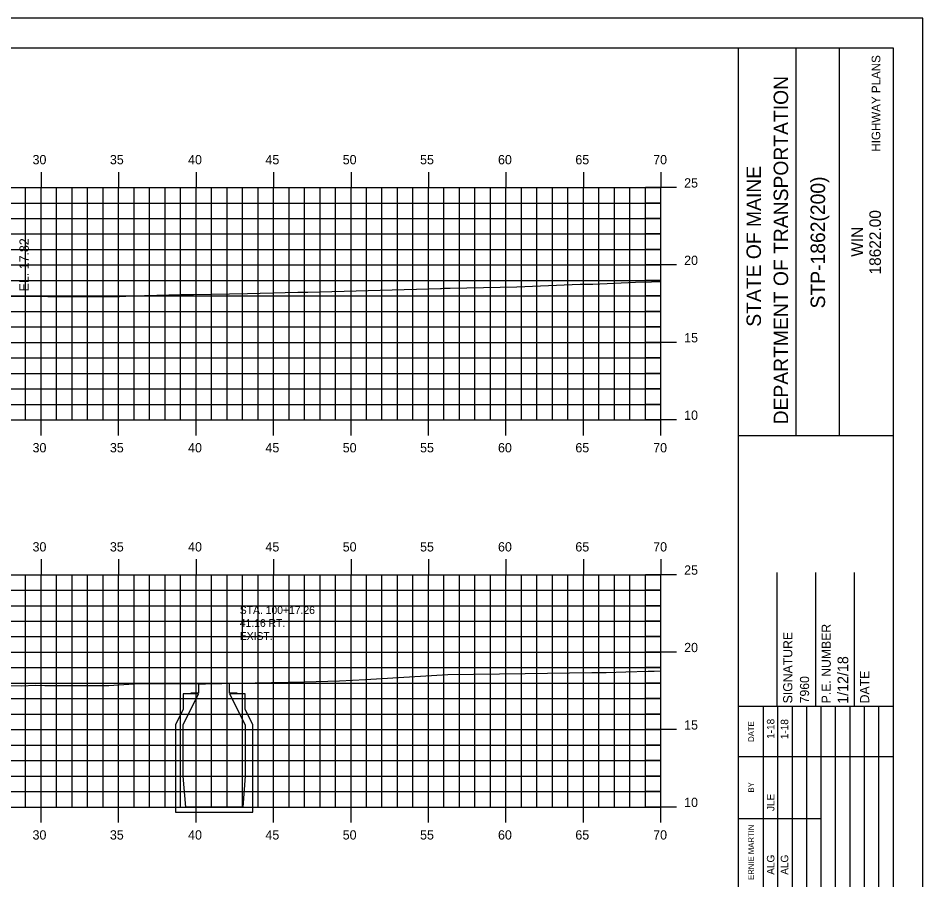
# Model space of a CAD drawing. Extents: x 1023237 to 1023407, y 394697 to 394807.
# Drawn here: x 1023348.2 to 1023406.6, y 394750.9 to 394806.5 of the extents above; entities that cross this region are included whole.
import ezdxf

# ---------------------------------------------------------------- set-up
doc = ezdxf.new("R2010")
doc.units = 0
for name, color, linetype in [('ANNOTATION', 7, 'Continuous'), ('BORDER', 7, 'Continuous'), ('D_Text_Monospaced', 7, 'Continuous'), ('H_V ANNOTATION', 7, 'Continuous'), ('HIGHWAY_TITLE', 7, 'Continuous'), ('MAJOR', 7, 'Continuous'), ('MINOR', 7, 'Continuous'), ('PLOT BOUNDARY', 7, 'Continuous'), ('S_Drainage_CB', 7, 'Continuous'), ('S_Roadway_Centerline', 7, 'Continuous')]:
    doc.layers.add(name, color=color, linetype=linetype)

msp = doc.modelspace()

# ---------------------------------------------------------------- linework, layer by layer
at = {"layer": 'BORDER'}
for p, q in [((1023404.664, 394804.607), (1023244.664, 394804.607)), ((1023394.664, 394699.607), (1023394.664, 394804.61)), ((1023398.392, 394779.604), (1023398.392, 394804.604)), ((1023401.187, 394779.604), (1023401.187, 394804.604)), ((1023404.664, 394699.607), (1023404.664, 394804.607)), ((1023394.664, 394779.601), (1023404.664, 394779.601)), ((1023397.164, 394762.11), (1023397.164, 394770.757)), ((1023399.664, 394762.11), (1023399.664, 394770.757)), ((1023402.164, 394762.11), (1023402.164, 394770.757)), ((1023394.664, 394762.11), (1023404.664, 394762.11))]:
    msp.add_line(p, q, dxfattribs=at)
for points in [[(1023396.278, 394758.86), (1023396.278, 394762.11)], [(1023397.211, 394744.613), (1023397.211, 394762.11)], [(1023398.143, 394762.11), (1023398.143, 394744.613)], [(1023399.074, 394744.613), (1023399.074, 394762.11)], [(1023400.006, 394744.613), (1023400.006, 394762.11)], [(1023400.938, 394744.613), (1023400.938, 394762.11)], [(1023401.869, 394744.613), (1023401.869, 394762.11)], [(1023402.801, 394744.613), (1023402.801, 394762.11)], [(1023403.733, 394744.613), (1023403.733, 394762.11)], [(1023396.279, 394744.613), (1023396.279, 394761.404)], [(1023394.664, 394758.86), (1023404.664, 394758.86)], [(1023394.664, 394754.86), (1023396.279, 394754.86)], [(1023396.278, 394754.86), (1023400.005, 394754.86)]]:
    msp.add_lwpolyline(points, dxfattribs=at)
at = {"layer": 'MAJOR'}
for p, q in [((1023349.663, 394796.609), (1023349.663, 394795.607)), ((1023354.663, 394796.609), (1023354.663, 394795.607)), ((1023359.663, 394796.609), (1023359.663, 394795.607)), ((1023364.663, 394796.609), (1023364.663, 394795.607)), ((1023369.663, 394796.609), (1023369.663, 394795.607)), ((1023374.663, 394796.609), (1023374.663, 394795.607)), ((1023379.663, 394796.609), (1023379.663, 394795.607)), ((1023384.663, 394796.609), (1023384.663, 394795.607)), ((1023389.663, 394796.609), (1023389.663, 394795.607)), ((1023249.663, 394795.607), (1023389.663, 394795.607)), ((1023349.663, 394780.607), (1023349.663, 394795.607)), ((1023354.663, 394780.607), (1023354.663, 394795.607)), ((1023359.663, 394780.607), (1023359.663, 394795.607)), ((1023364.663, 394780.607), (1023364.663, 394795.607)), ((1023369.663, 394780.607), (1023369.663, 394795.607)), ((1023374.663, 394780.607), (1023374.663, 394795.607)), ((1023379.663, 394780.607), (1023379.663, 394795.607)), ((1023384.663, 394780.607), (1023384.663, 394795.607)), ((1023390.665, 394795.607), (1023388.661, 394795.607)), ((1023389.663, 394780.607), (1023389.663, 394795.607)), ((1023249.663, 394790.607), (1023389.663, 394790.607)), ((1023390.665, 394790.607), (1023388.661, 394790.607)), ((1023249.663, 394785.607), (1023389.663, 394785.607)), ((1023390.665, 394785.607), (1023388.661, 394785.607)), ((1023249.663, 394780.607), (1023389.663, 394780.607)), ((1023349.663, 394779.605), (1023349.663, 394780.607)), ((1023354.663, 394779.605), (1023354.663, 394780.607)), ((1023359.663, 394779.605), (1023359.663, 394780.607)), ((1023364.663, 394779.605), (1023364.663, 394780.607)), ((1023369.663, 394779.605), (1023369.663, 394780.607)), ((1023374.663, 394779.605), (1023374.663, 394780.607)), ((1023379.663, 394779.605), (1023379.663, 394780.607)), ((1023384.663, 394779.605), (1023384.663, 394780.607)), ((1023390.665, 394780.607), (1023388.661, 394780.607)), ((1023389.663, 394779.605), (1023389.663, 394780.607)), ((1023349.663, 394771.609), (1023349.663, 394770.607)), ((1023354.663, 394771.609), (1023354.663, 394770.607)), ((1023359.663, 394771.609), (1023359.663, 394770.607)), ((1023364.663, 394771.609), (1023364.663, 394770.607)), ((1023369.663, 394771.609), (1023369.663, 394770.607)), ((1023374.663, 394771.609), (1023374.663, 394770.607)), ((1023379.663, 394771.609), (1023379.663, 394770.607)), ((1023384.663, 394771.609), (1023384.663, 394770.607)), ((1023389.663, 394771.609), (1023389.663, 394770.607)), ((1023249.663, 394770.607), (1023389.663, 394770.607)), ((1023349.663, 394755.607), (1023349.663, 394770.607)), ((1023354.663, 394755.607), (1023354.663, 394770.607)), ((1023359.663, 394755.607), (1023359.663, 394770.607)), ((1023364.663, 394755.607), (1023364.663, 394770.607)), ((1023369.663, 394755.607), (1023369.663, 394770.607)), ((1023374.663, 394755.607), (1023374.663, 394770.607)), ((1023379.663, 394755.607), (1023379.663, 394770.607)), ((1023384.663, 394755.607), (1023384.663, 394770.607)), ((1023390.665, 394770.607), (1023388.661, 394770.607)), ((1023389.663, 394755.607), (1023389.663, 394770.607)), ((1023249.663, 394765.607), (1023389.663, 394765.607)), ((1023390.665, 394765.607), (1023388.661, 394765.607)), ((1023249.663, 394760.607), (1023389.663, 394760.607)), ((1023390.665, 394760.607), (1023388.661, 394760.607)), ((1023249.663, 394755.607), (1023389.663, 394755.607)), ((1023349.663, 394754.605), (1023349.663, 394755.607)), ((1023354.663, 394754.605), (1023354.663, 394755.607)), ((1023359.663, 394754.605), (1023359.663, 394755.607)), ((1023364.663, 394754.605), (1023364.663, 394755.607)), ((1023369.663, 394754.605), (1023369.663, 394755.607)), ((1023374.663, 394754.605), (1023374.663, 394755.607)), ((1023379.663, 394754.605), (1023379.663, 394755.607)), ((1023384.663, 394754.605), (1023384.663, 394755.607)), ((1023390.665, 394755.607), (1023388.661, 394755.607)), ((1023389.663, 394754.605), (1023389.663, 394755.607))]:
    msp.add_line(p, q, dxfattribs=at)
at = {"layer": 'MINOR'}
for p, q in [((1023348.663, 394780.607), (1023348.663, 394795.607)), ((1023350.663, 394780.607), (1023350.663, 394795.607)), ((1023351.663, 394780.607), (1023351.663, 394795.607)), ((1023352.663, 394780.607), (1023352.663, 394795.607)), ((1023353.663, 394780.607), (1023353.663, 394795.607)), ((1023355.663, 394780.607), (1023355.663, 394795.607)), ((1023356.663, 394780.607), (1023356.663, 394795.607)), ((1023357.663, 394780.607), (1023357.663, 394795.607)), ((1023358.663, 394780.607), (1023358.663, 394795.607)), ((1023360.663, 394780.607), (1023360.663, 394795.607)), ((1023361.663, 394780.607), (1023361.663, 394795.607)), ((1023362.663, 394780.607), (1023362.663, 394795.607)), ((1023363.663, 394780.607), (1023363.663, 394795.607)), ((1023365.663, 394780.607), (1023365.663, 394795.607)), ((1023366.663, 394780.607), (1023366.663, 394795.607)), ((1023367.663, 394780.607), (1023367.663, 394795.607)), ((1023368.663, 394780.607), (1023368.663, 394795.607)), ((1023370.663, 394780.607), (1023370.663, 394795.607)), ((1023371.663, 394780.607), (1023371.663, 394795.607)), ((1023372.663, 394780.607), (1023372.663, 394795.607)), ((1023373.663, 394780.607), (1023373.663, 394795.607)), ((1023375.663, 394780.607), (1023375.663, 394795.607)), ((1023376.663, 394780.607), (1023376.663, 394795.607)), ((1023377.663, 394780.607), (1023377.663, 394795.607)), ((1023378.663, 394780.607), (1023378.663, 394795.607)), ((1023380.663, 394780.607), (1023380.663, 394795.607)), ((1023381.663, 394780.607), (1023381.663, 394795.607)), ((1023382.663, 394780.607), (1023382.663, 394795.607)), ((1023383.663, 394780.607), (1023383.663, 394795.607)), ((1023385.663, 394780.607), (1023385.663, 394795.607)), ((1023386.663, 394780.607), (1023386.663, 394795.607)), ((1023387.663, 394780.607), (1023387.663, 394795.607)), ((1023388.663, 394780.607), (1023388.663, 394795.607)), ((1023249.663, 394794.607), (1023389.663, 394794.607)), ((1023389.663, 394794.607), (1023388.661, 394794.607)), ((1023249.663, 394793.607), (1023389.663, 394793.607)), ((1023389.663, 394793.607), (1023388.661, 394793.607)), ((1023249.663, 394792.607), (1023389.663, 394792.607)), ((1023389.663, 394792.607), (1023388.661, 394792.607)), ((1023249.663, 394791.607), (1023389.663, 394791.607)), ((1023389.663, 394791.607), (1023388.661, 394791.607)), ((1023249.663, 394789.607), (1023389.663, 394789.607)), ((1023389.663, 394789.607), (1023388.661, 394789.607)), ((1023249.663, 394788.607), (1023389.663, 394788.607)), ((1023389.663, 394788.607), (1023388.661, 394788.607)), ((1023249.663, 394787.607), (1023389.663, 394787.607)), ((1023389.663, 394787.607), (1023388.661, 394787.607)), ((1023249.663, 394786.607), (1023389.663, 394786.607)), ((1023389.663, 394786.607), (1023388.661, 394786.607)), ((1023249.663, 394784.607), (1023389.663, 394784.607)), ((1023389.663, 394784.607), (1023388.661, 394784.607)), ((1023249.663, 394783.607), (1023389.663, 394783.607)), ((1023389.663, 394783.607), (1023388.661, 394783.607)), ((1023249.663, 394782.607), (1023389.663, 394782.607)), ((1023389.663, 394782.607), (1023388.661, 394782.607)), ((1023249.663, 394781.607), (1023389.663, 394781.607)), ((1023389.663, 394781.607), (1023388.661, 394781.607)), ((1023348.663, 394755.607), (1023348.663, 394770.607)), ((1023350.663, 394755.607), (1023350.663, 394770.607)), ((1023351.663, 394755.607), (1023351.663, 394770.607)), ((1023352.663, 394755.607), (1023352.663, 394770.607)), ((1023353.663, 394755.607), (1023353.663, 394770.607)), ((1023355.663, 394755.607), (1023355.663, 394770.607)), ((1023356.663, 394755.607), (1023356.663, 394770.607)), ((1023357.663, 394755.607), (1023357.663, 394770.607)), ((1023358.663, 394755.607), (1023358.663, 394770.607)), ((1023360.663, 394755.607), (1023360.663, 394770.607)), ((1023361.663, 394755.607), (1023361.663, 394770.607)), ((1023362.663, 394755.607), (1023362.663, 394770.607)), ((1023363.663, 394755.607), (1023363.663, 394770.607)), ((1023365.663, 394755.607), (1023365.663, 394770.607)), ((1023366.663, 394755.607), (1023366.663, 394770.607)), ((1023367.663, 394755.607), (1023367.663, 394770.607)), ((1023368.663, 394755.607), (1023368.663, 394770.607)), ((1023370.663, 394755.607), (1023370.663, 394770.607)), ((1023371.663, 394755.607), (1023371.663, 394770.607)), ((1023372.663, 394755.607), (1023372.663, 394770.607)), ((1023373.663, 394755.607), (1023373.663, 394770.607)), ((1023375.663, 394755.607), (1023375.663, 394770.607)), ((1023376.663, 394755.607), (1023376.663, 394770.607)), ((1023377.663, 394755.607), (1023377.663, 394770.607)), ((1023378.663, 394755.607), (1023378.663, 394770.607)), ((1023380.663, 394755.607), (1023380.663, 394770.607)), ((1023381.663, 394755.607), (1023381.663, 394770.607)), ((1023382.663, 394755.607), (1023382.663, 394770.607)), ((1023383.663, 394755.607), (1023383.663, 394770.607)), ((1023385.663, 394755.607), (1023385.663, 394770.607)), ((1023386.663, 394755.607), (1023386.663, 394770.607)), ((1023387.663, 394755.607), (1023387.663, 394770.607)), ((1023388.663, 394755.607), (1023388.663, 394770.607)), ((1023249.663, 394769.607), (1023389.663, 394769.607)), ((1023389.663, 394769.607), (1023388.661, 394769.607)), ((1023249.663, 394768.607), (1023389.663, 394768.607)), ((1023389.663, 394768.607), (1023388.661, 394768.607)), ((1023249.663, 394767.607), (1023389.663, 394767.607)), ((1023389.663, 394767.607), (1023388.661, 394767.607)), ((1023249.663, 394766.607), (1023389.663, 394766.607)), ((1023389.663, 394766.607), (1023388.661, 394766.607)), ((1023249.663, 394764.607), (1023389.663, 394764.607)), ((1023389.663, 394764.607), (1023388.661, 394764.607)), ((1023249.663, 394763.607), (1023389.663, 394763.607)), ((1023389.663, 394763.607), (1023388.661, 394763.607)), ((1023249.663, 394762.607), (1023389.663, 394762.607)), ((1023389.663, 394762.607), (1023388.661, 394762.607)), ((1023249.663, 394761.607), (1023389.663, 394761.607)), ((1023389.663, 394761.607), (1023388.661, 394761.607)), ((1023249.663, 394759.607), (1023389.663, 394759.607)), ((1023389.663, 394759.607), (1023388.661, 394759.607)), ((1023249.663, 394758.607), (1023389.663, 394758.607)), ((1023389.663, 394758.607), (1023388.661, 394758.607)), ((1023249.663, 394757.607), (1023389.663, 394757.607)), ((1023389.663, 394757.607), (1023388.661, 394757.607)), ((1023249.663, 394756.607), (1023389.663, 394756.607)), ((1023389.663, 394756.607), (1023388.661, 394756.607))]:
    msp.add_line(p, q, dxfattribs=at)
at = {"layer": 'PLOT BOUNDARY'}
msp.add_lwpolyline([(1023236.57, 394696.548), (1023406.57, 394696.548), (1023406.57, 394806.548), (1023236.57, 394806.548)], close=True, dxfattribs=at)
at = {"layer": 'S_Drainage_CB'}
for p, q in [((1023359.818, 394762.909), (1023358.834, 394762.909)), ((1023358.834, 394762.909), (1023358.834, 394761.925)), ((1023358.834, 394760.908), (1023359.818, 394762.909)), ((1023362.836, 394762.909), (1023361.819, 394762.909)), ((1023361.819, 394762.909), (1023362.836, 394760.908)), ((1023362.836, 394761.925), (1023362.836, 394762.909)), ((1023358.834, 394761.925), (1023358.342, 394760.908)), ((1023363.328, 394760.908), (1023362.836, 394761.925)), ((1023358.342, 394760.908), (1023358.342, 394755.265)), ((1023358.834, 394757.594), (1023358.834, 394760.908)), ((1023362.836, 394760.908), (1023362.836, 394757.594)), ((1023363.328, 394755.265), (1023363.328, 394760.908)), ((1023358.998, 394755.593), (1023358.834, 394757.594)), ((1023362.836, 394757.594), (1023362.672, 394755.593)), ((1023358.342, 394755.265), (1023363.328, 394755.265)), ((1023362.672, 394755.593), (1023358.998, 394755.593))]:
    msp.add_line(p, q, dxfattribs=at)
msp.add_lwpolyline([(1023362.311, 394762.951), (1023361.819, 394762.951), (1023361.819, 394763.574), (1023359.818, 394763.574), (1023359.818, 394762.951), (1023359.326, 394762.951)], dxfattribs=at)
at = {"layer": 'S_Roadway_Centerline'}
for points in [[(1023346.596, 394788.574), (1023349.311, 394788.598), (1023350.101, 394788.573), (1023350.826, 394788.572), (1023354.723, 394788.581), (1023355.539, 394788.614), (1023358.71, 394788.698), (1023359.504, 394788.705), (1023362.977, 394788.764), (1023366.237, 394788.847), (1023366.878, 394788.86), (1023375.443, 394789.095), (1023375.499, 394789.098), (1023375.676, 394789.108), (1023375.842, 394789.111), (1023376.072, 394789.114), (1023380.367, 394789.199), (1023383.943, 394789.34), (1023384.458, 394789.359), (1023384.523, 394789.359), (1023385.271, 394789.357), (1023388.026, 394789.491), (1023389.049, 394789.526), (1023389.663, 394789.535)], [(1023346.526, 394763.468), (1023348.384, 394763.423), (1023349.304, 394763.468), (1023349.911, 394763.459), (1023353.357, 394763.45), (1023353.798, 394763.449), (1023354.028, 394763.464), (1023355.978, 394763.593), (1023356.908, 394763.583), (1023359.813, 394763.554), (1023360.039, 394763.555), (1023360.164, 394763.558), (1023360.282, 394763.561), (1023366.66, 394763.688), (1023368.927, 394763.75), (1023370.597, 394763.849), (1023375.903, 394764.166), (1023380.896, 394764.237), (1023385.196, 394764.298), (1023386.138, 394764.29), (1023387.394, 394764.327), (1023388.842, 394764.377), (1023389.236, 394764.382), (1023389.663, 394764.393)]]:
    msp.add_lwpolyline(points, dxfattribs=at)

# ---------------------------------------------------------------- texts
at = {"layer": 'ANNOTATION'}
msp.add_text('EL. 17.82', height=0.6, rotation=90, dxfattribs=at).set_placement((1023348.867, 394788.896))
at = {"layer": 'BORDER'}
for s, height, p in [('DEPARTMENT OF TRANSPORTATION', 0.93176, (1023397.87, 394780.313)), ('STATE OF MAINE', 0.93176, (1023396.119, 394786.619)), ('STP-1862(200)', 0.93176, (1023400.256, 394787.801)), ('18622.00', 0.7453, (1023403.859, 394789.993)), ('WIN', 0.7453, (1023402.7, 394791.137)), ('P.E. NUMBER', 0.59055, (1023400.624, 394762.302)), ('SIGNATURE', 0.5906, (1023398.144, 394762.302)), ('1/12/18', 0.689, (1023401.752, 394762.273)), ('7960', 0.5906, (1023399.226, 394762.302)), ('DATE', 0.5906, (1023403.105, 394762.302)), ('DATE', 0.3714, (1023395.668, 394759.815)), ('1-18', 0.4845, (1023396.987, 394760.007)), ('1-18', 0.4845, (1023397.881, 394759.985)), ('BY', 0.3714, (1023395.668, 394756.545)), ('JLE', 0.4845, (1023396.987, 394755.345)), ('ERNIE MARTIN', 0.37275, (1023395.668, 394750.901)), ('ALG', 0.4845, (1023396.987, 394751.233)), ('ALG', 0.4845, (1023397.881, 394751.233))]:
    msp.add_text(s, height=height, rotation=90, dxfattribs=at).set_placement(p)
at = {"layer": 'D_Text_Monospaced'}
for s, height, p in [('STA. 100+17.26', 0.49998, (1023362.485, 394768.072)), ('41.16 RT.', 0.5, (1023362.485, 394767.238)), ('EXIST. ', 0.5, (1023362.485, 394766.398))]:
    msp.add_text(s, height=height, dxfattribs=at).set_placement(p)
at = {"layer": 'H_V ANNOTATION'}
for s, p in [('30', (1023349.112, 394797.107)), ('35', (1023354.104, 394797.107)), ('40', (1023359.15, 394797.107)), ('45', (1023364.142, 394797.107)), ('50', (1023369.128, 394797.107)), ('55', (1023374.12, 394797.107)), ('60', (1023379.15, 394797.107)), ('65', (1023384.142, 394797.107)), ('70', (1023389.165, 394797.107)), ('25', (1023391.163, 394795.607)), ('20', (1023391.163, 394790.607)), ('15', (1023391.163, 394785.607)), ('10', (1023391.163, 394780.607)), ('30', (1023349.112, 394778.507)), ('35', (1023354.104, 394778.507)), ('40', (1023359.15, 394778.507)), ('45', (1023364.142, 394778.507)), ('50', (1023369.128, 394778.507)), ('55', (1023374.12, 394778.507)), ('60', (1023379.15, 394778.507)), ('65', (1023384.142, 394778.507)), ('70', (1023389.165, 394778.507)), ('30', (1023349.112, 394772.107)), ('35', (1023354.104, 394772.107)), ('40', (1023359.15, 394772.107)), ('45', (1023364.142, 394772.107)), ('50', (1023369.128, 394772.107)), ('55', (1023374.12, 394772.107)), ('60', (1023379.15, 394772.107)), ('65', (1023384.142, 394772.107)), ('70', (1023389.165, 394772.107)), ('25', (1023391.163, 394770.607)), ('20', (1023391.163, 394765.607)), ('15', (1023391.163, 394760.607)), ('10', (1023391.163, 394755.607)), ('30', (1023349.112, 394753.507)), ('35', (1023354.104, 394753.507)), ('40', (1023359.15, 394753.507)), ('45', (1023364.142, 394753.507)), ('50', (1023369.128, 394753.507)), ('55', (1023374.12, 394753.507)), ('60', (1023379.15, 394753.507)), ('65', (1023384.142, 394753.507)), ('70', (1023389.165, 394753.507))]:
    msp.add_text(s, height=0.6, dxfattribs=at).set_placement(p)
at = {"layer": 'HIGHWAY_TITLE'}
msp.add_text('HIGHWAY PLANS', height=0.55901, rotation=90, dxfattribs=at).set_placement((1023403.822, 394797.922))

doc.saveas('drawing.dxf')
